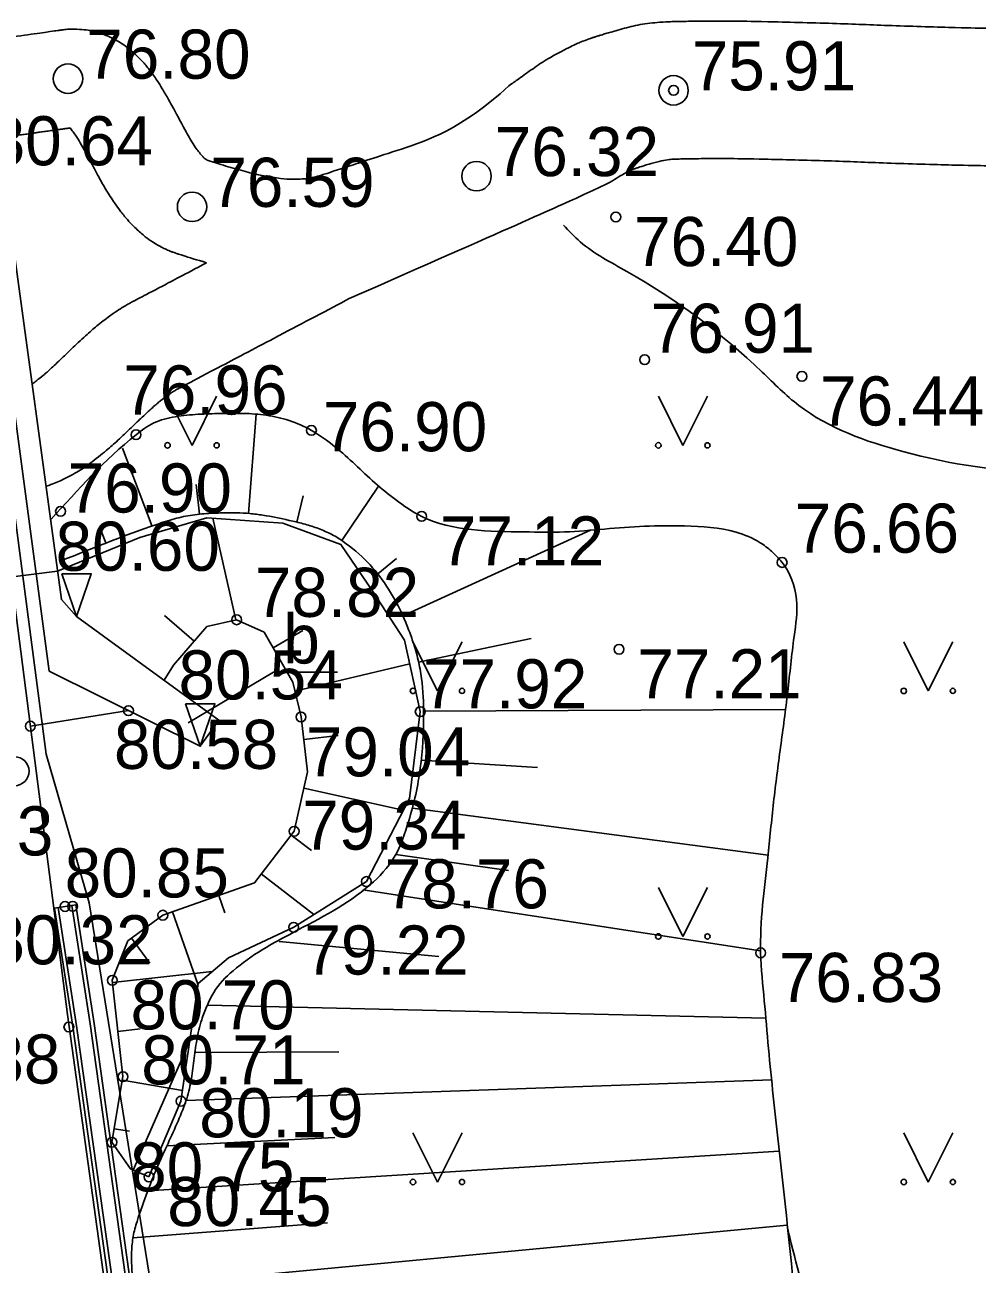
# Model space of a CAD drawing. Extents: x 576692 to 577659, y 273254 to 273799.
# Drawn here: x 576893.3 to 576903, y 273476.66 to 273489.28 of the extents above; entities that cross this region are included whole.
import ezdxf

# ---------------------------------------------------------------- set-up
doc = ezdxf.new("R2010")
doc.units = 0
for name, color, linetype in [('APGS_VADP_NEDR_####_#', 7, 'Continuous'), ('APGS_VADP_ZSPR_####_I', 7, 'Continuous'), ('BUVE_EKAS_####_####_#', 7, 'Continuous'), ('BUVE_EKAS_ADRS_TKST_#', 7, 'Continuous'), ('DREN_ELEM_####_####_#', 7, 'Continuous'), ('ELEK_VADP_ZSPR_TKST_#', 7, 'Continuous'), ('GAZE_ELEM_####_####_#', 7, 'Continuous'), ('GEOD_KORD_####_TKST_#', 7, 'Continuous'), ('GEOD_SITP_####_TKST_#', 7, 'Continuous'), ('HIDT_REZV_####_TKST_#', 7, 'Continuous'), ('Level 60', 7, 'Continuous'), ('LKAN_ELEM_PAST_TKST_#', 7, 'Continuous'), ('LKAN_VADP_PAST_####_I', 7, 'Continuous'), ('NORB_ZOGS_ZSTP_####_#', 7, 'Continuous'), ('RELJ_ELEM_####_####_#', 7, 'Continuous'), ('RELJ_NOGL_####_####_#', 7, 'Continuous'), ('SAKK_IZVK_####_TKST_#', 7, 'Continuous'), ('SAKT_ELEM_####_####_#', 7, 'Continuous'), ('TERT_KONT_####_####_#', 7, 'Continuous')]:
    doc.layers.add(name, color=color, linetype=linetype)

msp = doc.modelspace()

# ---------------------------------------------------------------- linework, layer by layer
at = {"layer": 'APGS_VADP_NEDR_####_#'}
msp.add_lwpolyline([(576894.561, 273477.551), (576894.887, 273478.323), (576895.061, 273479.522), (576895.371, 273479.782), (576896.035, 273480.093), (576896.776, 273480.559), (576897.214, 273481.405), (576897.324, 273482.289), (576897.164, 273483.016), (576896.833, 273483.523), (576896.517, 273483.991), (576895.925, 273484.207), (576895.15, 273484.262), (576894.469, 273484.063), (576893.629, 273483.72)], dxfattribs=at)
at = {"layer": 'BUVE_EKAS_####_####_#'}
for points in [[(576886.585, 273534.741), (576886.855, 273532.079), (576886.989, 273531.078), (576887.426, 273527.608), (576887.763, 273525.021), (576888.022, 273523.101), (576888.295, 273520.994), (576888.324, 273520.495), (576888.756, 273517.504), (576889.065, 273514.996), (576889.126, 273513.787), (576889.871, 273508.636), (576890.114, 273506.801), (576890.21, 273505.598), (576891.47, 273496.397), (576891.599, 273495.269), (576892.661, 273487.5), (576893.338, 273482.266), (576893.73, 273479.204), (576894.183, 273475.945)], [(576893.353, 273482.141), (576894.352, 273482.299)]]:
    msp.add_lwpolyline(points, dxfattribs=at)
at = {"layer": 'BUVE_EKAS_ADRS_TKST_#'}
for centre in [(576893.736, 273488.733), (576899.905, 273488.614), (576897.898, 273487.741), (576895, 273487.428)]:
    msp.add_circle(centre, 0.15, dxfattribs=at)
at = {"layer": 'DREN_ELEM_####_####_#'}
for p, q in [((576895.831, 273482.691), (576894.959, 273482.174)), ((576896.48, 273482.691), (576895.831, 273482.691))]:
    msp.add_line(p, q, dxfattribs=at)
for points in [[(576893.543, 273482.701), (576892.01, 273494.174)], [(576893.138, 273487.34), (576893.668, 273483.43), (576893.822, 273483.259), (576895.272, 273482.201), (576895.083, 273481.936), (576893.543, 273482.701)]]:
    msp.add_lwpolyline(points, dxfattribs=at)
at = {"layer": 'GAZE_ELEM_####_####_#'}
for p, q in [((576895.574, 273484.307), (576895.652, 273485.318)), ((576894.593, 273484.173), (576894.292, 273484.971)), ((576895.075, 273484.299), (576895.04, 273484.601)), ((576896.526, 273484.031), (576896.9, 273484.584)), ((576896.066, 273484.219), (576896.133, 273484.485)), ((576894.125, 273483.997), (576894.058, 273484.173)), ((576897.147, 273483.264), (576899.059, 273484.138)), ((576893.657, 273483.82), (576893.657, 273483.821)), ((576896.891, 273483.692), (576897.082, 273483.848)), ((576897.308, 273482.791), (576898.454, 273483.033)), ((576897.359, 273482.295), (576901.044, 273482.309)), ((576897.335, 273481.796), (576898.519, 273481.719)), ((576897.244, 273481.305), (576900.867, 273480.826)), ((576897.074, 273480.835), (576898.222, 273480.673)), ((576900.791, 273479.854), (576896.738, 273480.475)), ((576896.312, 273480.214), (576896.312, 273480.213)), ((576897.513, 273479.796), (576895.888, 273479.949)), ((576895.465, 273479.682), (576895.465, 273479.682)), ((576895.156, 273479.301), (576900.844, 273479.167)), ((576895.029, 273478.819), (576896.496, 273478.825)), ((576894.939, 273478.329), (576900.905, 273478.54)), ((576894.744, 273477.869), (576896.453, 273477.954)), ((576894.548, 273477.409), (576900.981, 273477.814)), ((576894.398, 273476.932), (576896.38, 273477.084)), ((576894.402, 273476.434), (576901.063, 273477.06))]:
    msp.add_line(p, q, dxfattribs=at)
msp.add_spline([(576893.657, 273483.82), (576894.708, 273484.217), (576894.888, 273484.269), (576895.075, 273484.299), (576895.265, 273484.311), (576895.453, 273484.313), (576895.587, 273484.306), (576895.722, 273484.289), (576895.99, 273484.236), (576896.133, 273484.202), (576896.272, 273484.159), (576896.406, 273484.101), (576896.473, 273484.065), (576896.538, 273484.022), (576896.786, 273483.811), (576896.981, 273483.568), (576897.132, 273483.297), (576897.195, 273483.151), (576897.25, 273483), (576897.303, 273482.813), (576897.337, 273482.627), (576897.359, 273482.254), (576897.325, 273481.715), (576897.278, 273481.446), (576897.207, 273481.176), (576897.06, 273480.808), (576896.811, 273480.524), (576896.035, 273480.043), (576895.417, 273479.65), (576895.22, 273479.43), (576895.152, 273479.293), (576895.098, 273479.151), (576895.048, 273478.945), (576895.018, 273478.735), (576894.989, 273478.526), (576894.937, 273478.323), (576894.845, 273478.092), (576894.742, 273477.865), (576894.639, 273477.636), (576894.546, 273477.403), (576894.439, 273477.099), (576894.4, 273476.946), (576894.384, 273476.79), (576894.396, 273476.496), (576894.429, 273476.203), (576894.478, 273475.818), (576894.59, 273474.778), (576894.685, 273473.93)], degree=3, dxfattribs=at)
at = {"layer": 'GEOD_KORD_####_TKST_#'}
for p, q in [((576895.444, 273483.222), (576895.21, 273484.258)), ((576895.02, 273483.005), (576894.718, 273483.267)), ((576895.825, 273482.94), (576896.128, 273483.114)), ((576896.048, 273482.496), (576897.218, 273482.774)), ((576894.717, 273482.609), (576894.716, 273482.61)), ((576896.137, 273482.005), (576896.487, 273482.046)), ((576896.138, 273481.511), (576897.152, 273481.285)), ((576896.01, 273481.032), (576896.215, 273480.874)), ((576895.705, 273480.636), (576896.241, 273480.223)), ((576895.271, 273480.418), (576895.333, 273480.242)), ((576894.8, 273480.251), (576895.06, 273479.515)), ((576894.383, 273479.981), (576894.57, 273479.728)), ((576894.19, 273479.53), (576895.204, 273479.642)), ((576894.245, 273479.033), (576894.472, 273479.058)), ((576894.399, 273477.622), (576894.976, 273478.938)), ((576894.29, 273478.536), (576894.903, 273478.433)), ((576894.206, 273478.043), (576894.364, 273478.016))]:
    msp.add_line(p, q, dxfattribs=at)
msp.add_lwpolyline([(576894.717, 273482.609), (576894.81, 273482.763), (576895.151, 273483.156), (576895.454, 273483.224), (576895.734, 273483.098), (576896.026, 273482.589), (576896.11, 273482.235), (576896.175, 273481.676), (576896.04, 273481.071), (576895.636, 273480.547), (576894.702, 273480.216), (576894.347, 273479.954), (576894.187, 273479.554), (576894.296, 273478.573), (576894.183, 273477.904), (576894.372, 273477.634), (576894.561, 273477.551)], dxfattribs=at)
at = {"layer": 'GEOD_SITP_####_TKST_#'}
for points in [[(576898.784, 273487.243), (576898.955, 273487.071), (576899.429, 273486.771), (576900.808, 273485.745), (576901.181, 273485.406), (576902.242, 273484.937), (576903.721, 273484.756), (576904.074, 273484.805), (576904.114, 273484.814)], [(576901.068, 273477.022), (576901.074, 273476.997), (576901.347, 273476.01), (576901.759, 273474.955), (576902.011, 273474.445), (576902.28, 273473.939), (576902.547, 273473.473), (576902.841, 273473.03), (576903.169, 273472.61), (576903.541, 273472.217), (576903.97, 273471.909), (576904.703, 273471.545), (576905.443, 273471.214), (576906.975, 273470.739), (576907.912, 273470.57), (576909.429, 273470.319), (576909.455, 273470.319), (576909.994, 273470.356), (576910.942, 273470.271), (576911.887, 273470.128), (576912.831, 273469.971), (576913.78, 273469.843), (576914.552, 273469.782), (576915.172, 273469.835), (576915.745, 273469.936), (576919.02, 273470.392), (576921.671, 273470.451), (576924.588, 273470.117), (576925.533, 273469.81), (576926.312, 273469.412), (576927.074, 273468.991), (576927.834, 273468.569), (576928.606, 273468.168), (576929.158, 273467.916), (576931.583, 273467.179), (576933.187, 273466.725), (576934.248, 273466.399), (576934.599, 273466.308), (576935.229, 273466.194), (576935.865, 273466.113), (576936.502, 273466.04), (576937.134, 273465.95), (576937.493, 273465.875), (576937.848, 273465.78), (576938.202, 273465.683), (576938.561, 273465.605), (576938.643, 273465.594)]]:
    msp.add_spline(points, degree=3, dxfattribs=at)
at = {"layer": 'Level 60'}
for points in [[(576893.597, 273480.288), (576893.815, 273480.322), (576894.003, 273479.115), (576894.444, 273475.956), (576894.492, 273475.54), (576894.889, 273471.925), (576895.03, 273470.791), (576895.598, 273466.48), (576895.925, 273464.522), (576896.152, 273462.503), (576896.374, 273460.63), (576896.43, 273460.261)], [(576893.597, 273480.288), (576893.785, 273479.083), (576894.226, 273475.928), (576894.274, 273475.516), (576894.671, 273471.891), (576894.812, 273470.762), (576895.38, 273466.448), (576895.707, 273464.492), (576895.934, 273462.477), (576896.156, 273460.602), (576896.234, 273460.026)], [(576893.637, 273480.294), (576893.824, 273479.089), (576894.266, 273475.933), (576894.313, 273475.52), (576894.711, 273471.897), (576894.852, 273470.767), (576895.42, 273466.454), (576895.747, 273464.497), (576895.973, 273462.482), (576896.196, 273460.607), (576896.274, 273460.032)], [(576893.775, 273480.314), (576893.963, 273479.109), (576894.404, 273475.951), (576894.453, 273475.536), (576894.849, 273471.919), (576894.99, 273470.786), (576895.558, 273466.474), (576895.885, 273464.517), (576896.113, 273462.498), (576896.334, 273460.625), (576896.39, 273460.256)]]:
    msp.add_lwpolyline(points, dxfattribs=at)
at = {"layer": 'LKAN_ELEM_PAST_TKST_#'}
for p, q in [((576894.75, 273485.5), (576895, 273485)), ((576895, 273485), (576895.25, 273485.5)), ((576899.75, 273485.5), (576900, 273485)), ((576900, 273485), (576900.25, 273485.5)), ((576897.25, 273483), (576897.5, 273482.5)), ((576897.5, 273482.5), (576897.75, 273483)), ((576902.25, 273483), (576902.5, 273482.5)), ((576902.5, 273482.5), (576902.75, 273483)), ((576899.75, 273480.5), (576900, 273480)), ((576900, 273480), (576900.25, 273480.5)), ((576897.25, 273478), (576897.5, 273477.5)), ((576897.5, 273477.5), (576897.75, 273478)), ((576902.25, 273478), (576902.5, 273477.5)), ((576902.5, 273477.5), (576902.75, 273478))]:
    msp.add_line(p, q, dxfattribs=at)
for centre, radius in [((576894.75, 273485), 0.028), ((576895.25, 273485), 0.0263), ((576899.75, 273485), 0.028), ((576900.25, 273485), 0.0263), ((576897.25, 273482.5), 0.028), ((576897.75, 273482.5), 0.0263), ((576902.25, 273482.5), 0.028), ((576902.75, 273482.5), 0.0263), ((576899.75, 273480), 0.028), ((576900.25, 273480), 0.0263), ((576897.25, 273477.5), 0.028), ((576897.75, 273477.5), 0.0263), ((576902.25, 273477.5), 0.028), ((576902.75, 273477.5), 0.0263)]:
    msp.add_circle(centre, radius, dxfattribs=at)
at = {"layer": 'LKAN_VADP_PAST_####_I'}
for points, degree in [([(576907.709, 273488.869), (576907.486, 273488.962), (576907.078, 273489.092), (576906.847, 273489.151), (576906.594, 273489.214), (576906.353, 273489.275), (576906.191, 273489.316), (576906.156, 273489.325), (576906.148, 273489.327), (576906.145, 273489.328), (576906.129, 273489.332), (576906.118, 273489.334), (576906.086, 273489.342), (576906.065, 273489.347), (576905.959, 273489.37), (576905.875, 273489.383), (576905.46, 273489.434), (576905.148, 273489.418), (576904.571, 273489.358), (576904.304, 273489.314), (576903.938, 273489.269), (576903.822, 273489.257), (576903.686, 273489.25), (576903.659, 273489.248), (576903.619, 273489.247), (576903.606, 273489.247), (576903.58, 273489.246), (576903.568, 273489.246), (576903.49, 273489.245), (576903.427, 273489.245), (576903.113, 273489.246), (576902.859, 273489.251), (576902.091, 273489.273), (576901.571, 273489.296), (576900.776, 273489.316), (576900.509, 273489.32), (576900.173, 273489.318), (576900.106, 273489.318), (576900.004, 273489.316), (576899.97, 273489.316), (576899.928, 273489.315), (576899.915, 273489.314), (576899.903, 273489.314), (576899.894, 273489.314), (576899.891, 273489.314), (576899.858, 273489.313), (576899.833, 273489.312), (576899.604, 273489.296), (576899.429, 273489.254), (576899.241, 273489.2), (576899.205, 273489.189), (576899.153, 273489.173), (576899.136, 273489.168), (576899.115, 273489.161), (576899.112, 273489.16), (576899.099, 273489.156), (576899.093, 273489.154), (576899.074, 273489.148), (576899.062, 273489.143), (576898.951, 273489.104), (576898.861, 273489.063), (576898.613, 273488.933), (576898.478, 273488.839), (576898.313, 273488.721), (576898.268, 273488.689), (576898.226, 273488.659)], 3), ([(576892.92, 273489.124), (576893.086, 273489.147), (576893.308, 273489.178), (576893.543, 273489.211), (576893.621, 273489.222), (576893.645, 273489.225), (576893.657, 273489.227), (576893.663, 273489.228), (576893.665, 273489.228), (576893.666, 273489.228), (576893.667, 273489.228), (576893.669, 273489.229), (576893.671, 273489.229), (576893.732, 273489.237), (576893.792, 273489.239), (576893.911, 273489.232), (576893.97, 273489.222), (576894.083, 273489.191), (576894.136, 273489.17), (576894.235, 273489.121), (576894.28, 273489.093), (576894.362, 273489.034), (576894.399, 273489.002), (576894.5, 273488.905), (576894.555, 273488.838), (576894.65, 273488.706), (576894.691, 273488.64), (576894.767, 273488.51), (576894.801, 273488.447), (576894.866, 273488.326), (576894.896, 273488.268), (576894.955, 273488.161), (576894.983, 273488.113), (576895.037, 273488.029), (576895.062, 273487.994), (576895.106, 273487.942), (576895.124, 273487.924), (576895.142, 273487.91), (576895.146, 273487.908), (576895.152, 273487.905), (576895.153, 273487.904), (576895.153, 273487.904)], 3), ([(576895.153, 273487.904), (576895.27, 273487.867), (576895.385, 273487.83), (576895.609, 273487.769), (576895.717, 273487.745), (576895.919, 273487.713), (576896.013, 273487.707), (576896.137, 273487.713), (576896.176, 273487.717), (576896.232, 273487.727), (576896.249, 273487.731), (576896.275, 273487.738), (576896.284, 273487.74), (576896.297, 273487.744), (576896.301, 273487.745), (576896.307, 273487.747), (576896.311, 273487.749), (576896.319, 273487.751), (576896.558, 273487.829), (576897.034, 273487.985), (576897.743, 273488.216), (576898.226, 273488.659)], 3), ([(576893.037, 273488.13), (576893.277, 273488.164), (576893.517, 273488.198), (576893.757, 273488.231)], 2), ([(576893.757, 273488.231), (576893.769, 273488.217), (576893.785, 273488.197), (576893.821, 273488.145), (576893.841, 273488.113), (576893.905, 273488.004), (576893.952, 273487.914), (576894.056, 273487.719), (576894.114, 273487.613), (576894.22, 273487.452), (576894.259, 273487.397), (576894.347, 273487.289), (576894.396, 273487.236), (576894.509, 273487.133), (576894.573, 273487.084), (576894.683, 273487.02), (576894.721, 273487.001), (576894.782, 273486.975), (576894.803, 273486.967), (576894.83, 273486.958), (576894.835, 273486.956), (576894.843, 273486.953), (576894.846, 273486.952), (576894.849, 273486.951), (576894.856, 273486.949), (576894.863, 273486.947), (576894.949, 273486.919), (576895.034, 273486.893), (576895.147, 273486.858)], 3), ([(576906.803, 273487.718), (576906.633, 273487.761), (576906.337, 273487.835), (576906.01, 273487.918), (576905.848, 273487.959), (576905.813, 273487.968), (576905.805, 273487.97), (576905.8, 273487.971), (576905.793, 273487.973), (576905.787, 273487.974), (576905.772, 273487.978), (576905.762, 273487.98), (576905.71, 273487.991), (576905.667, 273487.998), (576905.443, 273488.026), (576905.237, 273488.02), (576904.77, 273487.971), (576904.512, 273487.929), (576904.091, 273487.877), (576903.945, 273487.862), (576903.756, 273487.851), (576903.717, 273487.85), (576903.66, 273487.848), (576903.64, 273487.847), (576903.601, 273487.846), (576903.58, 273487.846), (576903.496, 273487.845), (576903.429, 273487.845), (576903.094, 273487.846), (576902.827, 273487.851), (576902.036, 273487.874), (576901.516, 273487.897), (576900.751, 273487.916), (576900.498, 273487.92), (576900.185, 273487.919), (576900.122, 273487.918), (576900.029, 273487.916), (576899.997, 273487.916), (576899.958, 273487.915), (576899.947, 273487.915), (576899.935, 273487.915), (576899.927, 273487.914), (576899.922, 273487.914), (576899.915, 273487.914), (576899.908, 273487.914), (576899.845, 273487.909), (576899.766, 273487.894), (576899.639, 273487.858), (576899.612, 273487.85), (576899.57, 273487.836), (576899.555, 273487.832), (576899.537, 273487.826), (576899.533, 273487.825), (576899.53, 273487.824), (576899.528, 273487.823), (576899.524, 273487.822), (576899.521, 273487.821), (576899.492, 273487.811), (576899.463, 273487.798), (576899.396, 273487.763), (576899.342, 273487.731), (576899.223, 273487.65), (576898.216, 273487.205), (576896.601, 273486.494)], 3), ([(576893.377, 273485.63), (576893.393, 273485.641), (576893.41, 273485.654), (576893.488, 273485.715), (576893.554, 273485.775), (576893.698, 273485.91), (576893.774, 273485.986), (576893.943, 273486.142), (576894.034, 273486.222), (576894.19, 273486.338), (576894.245, 273486.376), (576894.333, 273486.429), (576894.363, 273486.446), (576894.403, 273486.467), (576894.407, 273486.469), (576894.418, 273486.475), (576894.435, 273486.484), (576894.679, 273486.612), (576894.919, 273486.738), (576895.147, 273486.858)], 3), ([(576893.516, 273484.584), (576893.585, 273484.607), (576893.65, 273484.635), (576893.838, 273484.729), (576893.948, 273484.805), (576894.144, 273484.959), (576894.232, 273485.039), (576894.393, 273485.192), (576894.468, 273485.265), (576894.608, 273485.395), (576894.674, 273485.452), (576894.765, 273485.519), (576894.794, 273485.539), (576894.835, 273485.564), (576894.849, 273485.572), (576894.865, 273485.58), (576894.872, 273485.584), (576894.883, 273485.59), (576894.9, 273485.599), (576895.273, 273485.795), (576895.842, 273486.094), (576896.399, 273486.388), (576896.601, 273486.494)], 3)]:
    msp.add_open_spline(points, degree=degree, dxfattribs=at)
at = {"layer": 'RELJ_ELEM_####_####_#'}
for points in [[(576893.672, 273483.692), (576893.972, 273483.692), (576893.822, 273483.259)], [(576894.933, 273482.369), (576895.233, 273482.369), (576895.083, 273481.936)]]:
    msp.add_lwpolyline(points, close=True, dxfattribs=at)
for centre in [(576899.905, 273488.614), (576899.317, 273487.325), (576899.61, 273485.872), (576901.212, 273485.702), (576894.429, 273485.108), (576896.216, 273485.152), (576893.66, 273484.329), (576897.339, 273484.277), (576901.011, 273483.808), (576895.454, 273483.224), (576899.35, 273482.924), (576894.352, 273482.299), (576896.11, 273482.235), (576897.324, 273482.289), (576893.353, 273482.141), (576896.04, 273481.071), (576896.776, 273480.559), (576893.706, 273480.305), (576893.783, 273480.306), (576894.702, 273480.216), (576896.035, 273480.093), (576900.792, 273479.833), (576894.187, 273479.554), (576893.745, 273479.079), (576894.296, 273478.573), (576894.887, 273478.323), (576894.183, 273477.904), (576894.561, 273477.551)]:
    msp.add_circle(centre, 0.05, dxfattribs=at)
at = {"layer": 'RELJ_NOGL_####_####_#'}
msp.add_line((576889.347, 273483.173), (576893.629, 273483.72), dxfattribs=at)
at = {"layer": 'SAKK_IZVK_####_TKST_#'}
msp.add_lwpolyline([(576942.692, 273556.432), (576946.393, 273539.221), (576939.29, 273532.022), (576922.073, 273527.846), (576918.805, 273527.051), (576907.929, 273524.455), (576902.076, 273522.759), (576898.608, 273522.684), (576896.296, 273522.291), (576891.404, 273520.162), (576890.218, 273511.878), (576891.417, 273501.862), (576891.831, 273497.397), (576891.831, 273494.655), (576893.512, 273481.855), (576893.95, 273480.341), (576897.225, 273460.097), (576898.516, 273450.643), (576898.904, 273444.378)], dxfattribs=at)
at = {"layer": 'SAKT_ELEM_####_####_#'}
msp.add_spline([(576893.566, 273484.248), (576894.429, 273485.108), (576894.611, 273485.229), (576894.829, 273485.291), (576895.062, 273485.316), (576895.289, 273485.324), (576895.521, 273485.325), (576895.756, 273485.306), (576895.988, 273485.253), (576896.216, 273485.152), (576896.455, 273484.986), (576896.662, 273484.804), (576896.86, 273484.62), (576897.071, 273484.448), (576897.339, 273484.277), (576898.385, 273484.119), (576898.793, 273484.119), (576899.201, 273484.148), (576899.61, 273484.177), (576900.018, 273484.179), (576900.542, 273484.116), (576900.787, 273484.009), (576900.902, 273483.922), (576900.957, 273483.869), (576901.011, 273483.808), (576901.158, 273483.432), (576901.133, 273483.053), (576901.068, 273482.491), (576900.995, 273481.928), (576900.924, 273481.366), (576900.864, 273480.802), (576900.792, 273479.833), (576900.829, 273479.346), (576900.872, 273478.86), (576900.974, 273477.887), (576901.179, 273475.941), (576901.399, 273473.457)], degree=3, dxfattribs=at)
at = {"layer": 'TERT_KONT_####_####_#'}
msp.add_circle((576893.191, 273481.682), 0.148, dxfattribs=at)

# ---------------------------------------------------------------- texts
at = {"layer": 'APGS_VADP_ZSPR_####_I'}
msp.add_text('b', height=0.5, dxfattribs=at).set_placement((576895.929, 273482.779))
at = {"layer": 'ELEK_VADP_ZSPR_TKST_#'}
msp.add_text(' 80.83', height=0.5, dxfattribs=at).set_placement((576891.727, 273480.825))
at = {"layer": 'HIDT_REZV_####_TKST_#'}
for s, p in [(' 80.64', (576892.742, 273487.851)), (' 76.40', (576899.317, 273486.825)), (' 76.91', (576899.487, 273485.942)), (' 76.96', (576894.113, 273485.314)), (' 76.44', (576901.212, 273485.202)), (' 76.90', (576896.147, 273484.94)), (' 76.90', (576893.547, 273484.316)), (' 76.66', (576900.954, 273483.907)), (' 77.12', (576897.339, 273483.777)), (' 80.60', (576893.424, 273483.723)), (' 78.82', (576895.454, 273483.254)), (' 80.54', (576894.676, 273482.413)), (' 77.21', (576899.35, 273482.424)), (' 77.92', (576897.167, 273482.322)), (' 80.58', (576894.018, 273481.706)), (' 79.04', (576895.974, 273481.63)), (' 79.34', (576895.936, 273480.884)), (' 80.85', (576893.516, 273480.397)), (' 78.76', (576896.776, 273480.286)), (' 80.32', (576892.739, 273479.716)), (' 79.22', (576895.959, 273479.612)), (' 76.83', (576900.792, 273479.333)), (' 80.70', (576894.187, 273479.054)), (' 80.88', (576891.799, 273478.502)), (' 80.71', (576894.296, 273478.494)), (' 80.19', (576894.887, 273477.955)), (' 80.75', (576894.183, 273477.404)), (' 80.45', (576894.561, 273477.051))]:
    msp.add_text(s, height=0.5, dxfattribs=at).set_placement(p)
at = {"layer": 'NORB_ZOGS_ZSTP_####_#'}
for s, p in [(' 76.80', (576893.736, 273488.733)), (' 75.91', (576899.905, 273488.614)), (' 76.32', (576897.898, 273487.741)), (' 76.59', (576895, 273487.428))]:
    msp.add_text(s, height=0.5, dxfattribs=at).set_placement(p)

doc.saveas('drawing.dxf')
